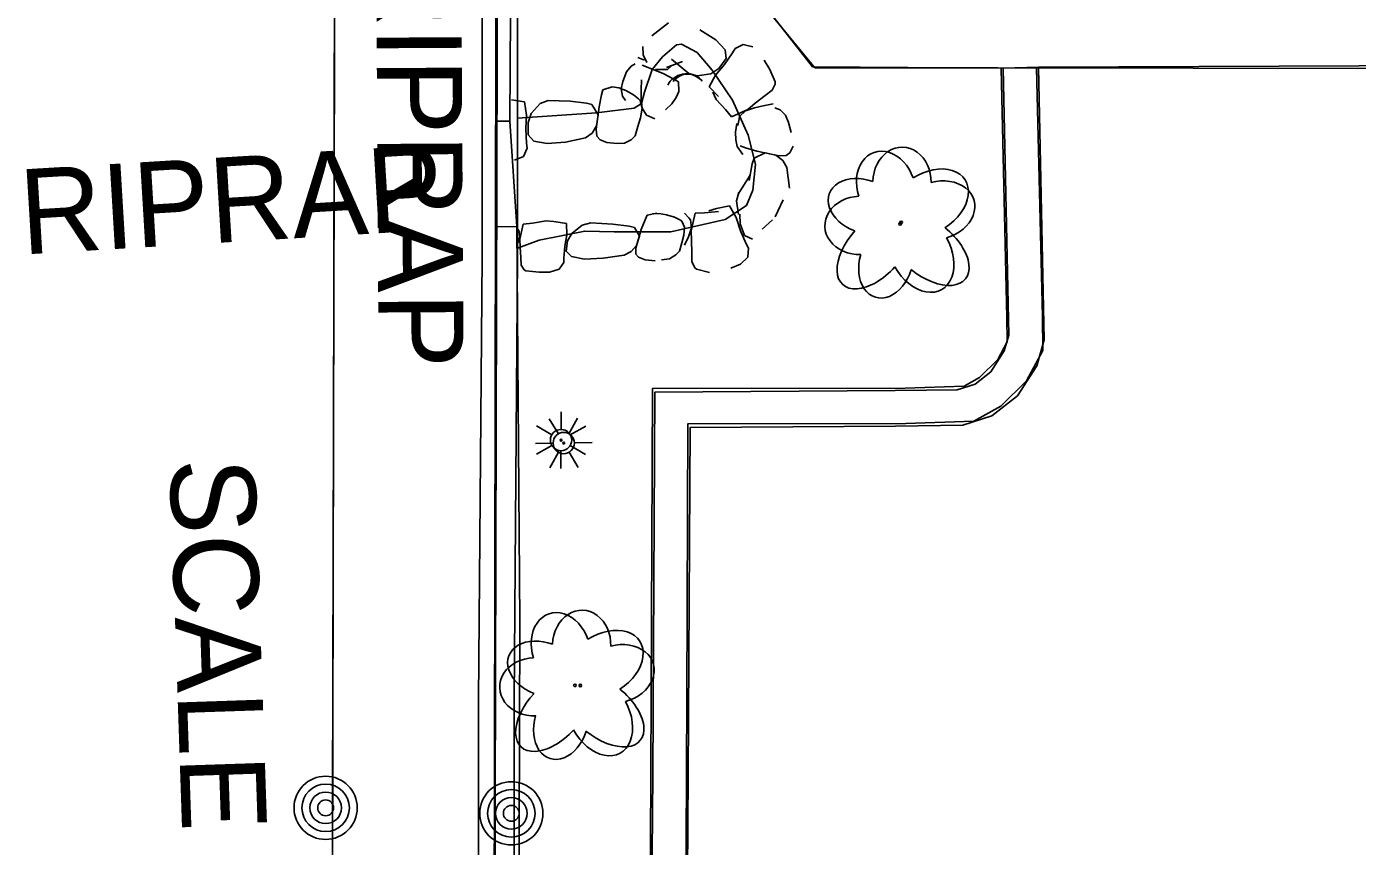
# Model space of a CAD drawing. Extents: x 588843 to 2552415, y 180129 to 269402.
# Drawn here: x 594379 to 594472.9, y 184860.3 to 184918.1 of the extents above; entities that cross this region are included whole.
import ezdxf

# ---------------------------------------------------------------- set-up
doc = ezdxf.new("R2010")
doc.units = 0
for name, color, linetype in [('Default', 7, 'Continuous'), ('E_BLD_Dash', 7, 'Continuous'), ('E_BLD_HvyDash', 7, 'Continuous'), ('E_BLD_Text', 7, 'Continuous'), ('E_DRN', 7, 'Continuous'), ('E_DRN_RipRap', 7, 'Continuous'), ('E_DRN_RipRap_Text', 7, 'Continuous'), ('E_DWY', 7, 'Continuous'), ('E_LAND_Vegetation', 7, 'Continuous'), ('E_LTG', 7, 'Continuous'), ('E_MISCPROP', 7, 'Continuous'), ('E_PATH_Sidewalk', 7, 'Continuous')]:
    doc.layers.add(name, color=color, linetype=linetype)

# ---------------------------------------------------------------- blocks, each defined once
blk = doc.blocks.new('POLE')
at = {"layer": 'Default'}
for radius in [4.46, 3.35, 2.23, 1.12]:
    blk.add_circle((0, 0), radius, dxfattribs=at)
blk = doc.blocks.new('LPOL')
at = {"layer": 'Default'}
for p, q in [((-0.75, 1.3), (-2, 3.46)), ((0.75, 1.3), (2, 3.46)), ((-4, 0), (-1.5, 0)), ((1.5, 0), (4, 0)), ((-2, -3.46), (-0.75, -1.3)), ((2, -3.46), (0.75, -1.3))]:
    blk.add_line(p, q, dxfattribs=at)
for radius in [1.5, 1.5, 1.5, 0.125]:
    blk.add_circle((0, 0), radius, dxfattribs=at)
blk = doc.blocks.new('DTRE')
at = {"layer": 'Default'}
blk.add_circle((-0.18, 0), 0.183, dxfattribs=at)
for centre, major_axis, ratio in [((-1.87, 5.32), (1.36, -4.98), 0.782863), ((4.06, 2.74), (-5.27, -2.93), 0.691916), ((-5.87, 0.15), (4.93, -0.12), 0.832022), ((3.54, -3.71), (-5.01, 4.58), 0.560249), ((-2.49, -5.24), (1.8, 4.86), 0.716896)]:
    blk.add_ellipse(centre, major_axis=major_axis, ratio=ratio, start_param=1.570796, end_param=4.712389, dxfattribs=at)
blk = doc.blocks.new('CULV2')
at = {"layer": 'E_DRN'}
blk.add_arc((19.7, 14.8), 24.6, 216.8699, 323.1301, dxfattribs=at)
blk = doc.blocks.new('RIPRT')
at = {"layer": 'E_DRN_RipRap_Text'}
blk.add_text('RIPRAP', height=12, dxfattribs=at).set_placement((-0.14, -3.59))
blk = doc.blocks.new('LPOL_4')
at = {"layer": 'E_LTG'}
for p, q in [((-2.46, 4.26), (-6.56, 11.36)), ((2.46, 4.26), (6.56, 11.36)), ((-13.12, 0), (-4.92, 0)), ((4.92, 0), (13.12, 0)), ((-6.56, -11.36), (-2.46, -4.26)), ((6.56, -11.36), (2.46, -4.26))]:
    blk.add_line(p, q, dxfattribs=at)
for radius in [4.92, 4.92, 4.92, 0.41]:
    blk.add_circle((0, 0), radius, dxfattribs=at)
blk = doc.blocks.new('RIPRT_3')
at = {"layer": 'E_DRN_RipRap_Text'}
blk.add_text('RIPRAP', height=39.37, dxfattribs=at).set_placement((-0.46, -11.78))
blk = doc.blocks.new('SCAL_1')
at = {"layer": 'E_BLD_HvyDash'}
blk.add_text('SCALE', height=39.37, dxfattribs=at).set_placement((-86.45, -19.68))
blk = doc.blocks.new('CULV2_4')
at = {"layer": 'E_DRN'}
blk.add_arc((64.6, 48.4), 80.7, 216.8699, 323.1301, dxfattribs=at)
blk = doc.blocks.new('DTRE_4')
at = {"layer": 'E_LAND_Vegetation'}
blk.add_circle((-0.6, 0), 0.601, dxfattribs=at)
for centre, major_axis, ratio in [((-6.14, 17.45), (4.46, -16.34), 0.782863), ((13.31, 8.98), (-17.3, -9.61), 0.691916), ((-19.26, 0.5), (16.18, -0.4), 0.832022), ((11.62, -12.16), (-16.44, 15.03), 0.560249), ((-8.18, -17.2), (5.91, 15.93), 0.716896)]:
    blk.add_ellipse(centre, major_axis=major_axis, ratio=ratio, start_param=1.570796, end_param=4.712389, dxfattribs=at)

msp = doc.modelspace()

# ---------------------------------------------------------------- linework, layer by layer
at = {"layer": 'E_BLD_Dash'}
msp.add_lwpolyline([(594400.82, 184942.865), (594400.287, 184739.801), (594411.764, 184739.77), (594412.297, 184942.833)], close=True, dxfattribs=at)
at = {"layer": 'E_BLD_HvyDash'}
msp.add_lwpolyline([(594412.167, 184942.934), (594411.807, 184740.073), (594400.358, 184739.937), (594400.801, 184943.059), (594412.167, 184942.934)], close=True, dxfattribs=at)
at = {"layer": 'E_DRN_RipRap'}
for p, q in [((594423.142, 184917.475), (594424.299, 184918.399)), ((594426.528, 184917.92), (594427.655, 184917.206)), ((594427.655, 184917.206), (594428.308, 184916.491)), ((594429.57, 184916.883), (594429.004, 184916.597)), ((594430.247, 184916.718), (594429.57, 184916.883)), ((594422.152, 184915.969), (594422.605, 184915.758)), ((594422.5, 184916.728), (594422.523, 184916.157)), ((594422.523, 184916.157), (594422.791, 184915.605)), ((594425.738, 184914.832), (594424.516, 184915.83)), ((594428.378, 184915.882), (594427.857, 184915.189)), ((594428.823, 184916.276), (594428.253, 184915.461)), ((594428.308, 184916.491), (594428.378, 184915.882)), ((594429.004, 184916.597), (594428.823, 184916.276)), ((594421.096, 184914.273), (594421.343, 184914.948)), ((594421.343, 184914.948), (594421.668, 184915.351)), ((594421.668, 184915.351), (594421.963, 184915.499)), ((594422.457, 184915.426), (594423.935, 184914.817)), ((594422.679, 184915.333), (594423.393, 184915.03)), ((594424.242, 184915.1), (594423.388, 184915.108)), ((594425.293, 184915.674), (594424.172, 184915.258)), ((594424.54, 184915.382), (594424.242, 184915.1)), ((594427.857, 184915.189), (594427.292, 184914.811)), ((594428.253, 184915.461), (594427.634, 184914.711)), ((594431.45, 184915.113), (594431.06, 184915.763)), ((594431.83, 184914.238), (594431.45, 184915.113)), ((594420.961, 184913.754), (594421.096, 184914.273)), ((594422.379, 184913.684), (594422.396, 184914.387)), ((594423.935, 184914.817), (594424.685, 184914.432)), ((594424.685, 184914.432), (594425.019, 184914.235)), ((594425.019, 184914.235), (594425.036, 184913.558)), ((594426.34, 184914.655), (594425.738, 184914.832)), ((594427.292, 184914.811), (594426.34, 184914.655)), ((594427.634, 184914.711), (594427.179, 184913.879)), ((594431.612, 184913.658), (594431.835, 184914.084)), ((594431.835, 184914.084), (594431.83, 184914.238)), ((594419.409, 184912.486), (594419.585, 184913.312)), ((594419.585, 184913.312), (594419.688, 184913.687)), ((594419.688, 184913.687), (594420.337, 184913.885)), ((594420.337, 184913.885), (594420.803, 184913.81)), ((594420.803, 184913.81), (594421.301, 184913.636)), ((594421.069, 184913.241), (594420.961, 184913.754)), ((594421.269, 184912.915), (594421.069, 184913.241)), ((594421.301, 184913.636), (594421.83, 184913.329)), ((594421.83, 184913.329), (594422.183, 184913.036)), ((594422.183, 184913.036), (594422.316, 184912.914)), ((594422.373, 184913.037), (594422.379, 184913.684)), ((594422.454, 184912.371), (594422.373, 184913.037)), ((594424.84, 184913.13), (594424.539, 184912.696)), ((594425.036, 184913.558), (594424.84, 184913.13)), ((594427.179, 184913.879), (594427.826, 184913.2)), ((594427.434, 184913.506), (594427.666, 184913.003)), ((594427.666, 184913.003), (594428.325, 184912.277)), ((594430.431, 184912.736), (594431.115, 184913.273)), ((594431.115, 184913.273), (594431.612, 184913.658)), ((594414.15, 184912.822), (594413.247, 184912.973)), ((594414.289, 184911.885), (594414.15, 184912.822)), ((594414.614, 184912.011), (594415.259, 184912.711)), ((594415.259, 184912.711), (594415.83, 184912.933)), ((594415.83, 184912.933), (594417.367, 184912.876)), ((594417.367, 184912.876), (594418.525, 184912.743)), ((594418.525, 184912.743), (594418.912, 184912.637)), ((594418.912, 184912.637), (594419.345, 184911.906)), ((594419.206, 184910.898), (594419.409, 184912.486)), ((594422.316, 184912.914), (594422.454, 184912.371)), ((594422.454, 184912.371), (594422.344, 184911.71)), ((594422.745, 184911.892), (594422.454, 184912.371)), ((594424.539, 184912.696), (594424.102, 184912.267)), ((594428.325, 184912.277), (594428.748, 184911.769)), ((594428.748, 184911.769), (594429.901, 184912.299)), ((594429.323, 184911.798), (594429.728, 184912.186)), ((594429.728, 184912.186), (594430.361, 184912.409)), ((594429.901, 184912.299), (594430.431, 184912.736)), ((594430.361, 184912.409), (594430.994, 184912.542)), ((594430.994, 184912.542), (594431.685, 184912.677)), ((594431.816, 184912.411), (594432.174, 184912.254)), ((594432.174, 184912.254), (594432.567, 184911.887)), ((594414.254, 184910.913), (594414.289, 184911.885)), ((594414.4, 184911.369), (594414.614, 184912.011)), ((594414.406, 184910.502), (594414.4, 184911.369)), ((594418.917, 184910.619), (594419.239, 184911.136)), ((594419.239, 184911.136), (594419.345, 184911.906)), ((594422.344, 184911.71), (594422.157, 184911.092)), ((594422.911, 184911.814), (594422.745, 184911.892)), ((594423.341, 184911.639), (594422.911, 184911.814)), ((594429.032, 184910.684), (594429.131, 184911.299)), ((594429.204, 184911.162), (594429.283, 184911.62)), ((594429.283, 184911.62), (594429.323, 184911.798)), ((594432.567, 184911.887), (594432.767, 184911.373)), ((594432.767, 184911.373), (594432.969, 184910.662)), ((594414.294, 184909.919), (594414.254, 184910.913)), ((594414.819, 184910.059), (594414.406, 184910.502)), ((594418.455, 184910.299), (594417.045, 184909.995)), ((594418.455, 184910.299), (594418.917, 184910.619)), ((594419.265, 184910.402), (594419.206, 184910.898)), ((594419.486, 184910.157), (594419.265, 184910.402)), ((594421.946, 184910.424), (594421.682, 184910.144)), ((594422.157, 184911.092), (594421.946, 184910.424)), ((594429.046, 184910.144), (594429.032, 184910.684)), ((594414.074, 184908.984), (594414.343, 184909.554)), ((594414.343, 184909.554), (594414.294, 184909.919)), ((594415.749, 184909.884), (594414.819, 184910.059)), ((594417.045, 184909.995), (594415.749, 184909.884)), ((594419.96, 184909.951), (594419.486, 184910.157)), ((594420.678, 184909.893), (594419.96, 184909.951)), ((594421.215, 184909.902), (594420.678, 184909.893)), ((594421.682, 184910.144), (594421.215, 184909.902)), ((594429.142, 184909.67), (594429.046, 184910.144)), ((594429.56, 184909.113), (594429.142, 184909.67)), ((594429.73, 184909.588), (594429.365, 184909.722)), ((594430.541, 184909.344), (594429.73, 184909.588)), ((594430.353, 184908.847), (594431.114, 184909.234)), ((594432.109, 184909.014), (594430.541, 184909.344)), ((594431.873, 184909.066), (594431.114, 184909.234)), ((594432.869, 184909.243), (594432.608, 184909.036)), ((594433.109, 184909.713), (594432.869, 184909.243)), ((594413.452, 184908.707), (594414.074, 184908.984)), ((594429.997, 184907.283), (594430.218, 184908.458)), ((594430.218, 184908.458), (594430.353, 184908.847)), ((594432.365, 184908.697), (594431.873, 184909.066)), ((594432.608, 184909.036), (594432.109, 184909.014)), ((594432.649, 184908.199), (594432.365, 184908.697)), ((594429.231, 184906.313), (594430.069, 184907.651)), ((594432.649, 184908.199), (594432.845, 184906.731)), ((594429.094, 184905.841), (594429.279, 184906.441)), ((594428.613, 184905.485), (594427.693, 184905.296)), ((594429.077, 184904.659), (594428.613, 184905.485)), ((594429.24, 184904.887), (594429.094, 184905.841)), ((594432.392, 184905.915), (594431.823, 184904.707)), ((594422.666, 184904.515), (594422.814, 184904.827)), ((594422.814, 184904.827), (594423.494, 184904.976)), ((594423.178, 184904.937), (594423.656, 184904.941)), ((594423.656, 184904.941), (594424.175, 184904.867)), ((594424.175, 184904.867), (594424.735, 184904.688)), ((594424.735, 184904.688), (594425.115, 184904.495)), ((594425.432, 184904.983), (594425.747, 184904.643)), ((594425.747, 184904.643), (594425.864, 184904.502)), ((594426.19, 184904.977), (594425.911, 184903.739)), ((594426.848, 184905.005), (594426.19, 184904.977)), ((594427.824, 184905.087), (594426.848, 184905.005)), ((594427.693, 184905.296), (594427.162, 184905.141)), ((594429.385, 184903.737), (594429.077, 184904.659)), ((594429.365, 184904.217), (594429.343, 184904.896)), ((594413.627, 184903.872), (594413.747, 184903.766)), ((594413.747, 184903.766), (594413.824, 184903.307)), ((594414.057, 184904.193), (594413.814, 184903.134)), ((594414.711, 184904.278), (594414.057, 184904.193)), ((594415.677, 184904.439), (594414.711, 184904.278)), ((594416.215, 184904.389), (594415.677, 184904.439)), ((594417.111, 184904.24), (594416.215, 184904.389)), ((594417.143, 184903.45), (594417.111, 184904.24)), ((594417.486, 184903.548), (594418.22, 184904.119)), ((594418.22, 184904.119), (594418.824, 184904.291)), ((594418.824, 184904.291), (594420.372, 184904.205)), ((594420.372, 184904.205), (594421.527, 184904.064)), ((594421.527, 184904.064), (594421.907, 184903.965)), ((594421.907, 184903.965), (594422.26, 184903.342)), ((594422.003, 184902.5), (594422.392, 184903.826)), ((594422.392, 184903.826), (594422.666, 184904.515)), ((594425.115, 184904.495), (594425.259, 184904.413)), ((594425.259, 184904.413), (594425.441, 184903.983)), ((594425.441, 184903.983), (594425.379, 184903.42)), ((594425.926, 184903.945), (594425.72, 184903.307)), ((594425.864, 184904.502), (594425.926, 184903.945)), ((594425.911, 184903.739), (594425.937, 184903.052)), ((594429.676, 184903.408), (594429.365, 184904.217)), ((594429.775, 184902.822), (594429.385, 184903.737)), ((594431.631, 184904.5), (594430.908, 184903.853)), ((594413.824, 184903.307), (594413.636, 184902.756)), ((594413.814, 184903.134), (594413.858, 184902.564)), ((594416.994, 184902.636), (594417.143, 184903.45)), ((594417.1, 184902.288), (594417.195, 184903.015)), ((594417.195, 184903.015), (594417.486, 184903.548)), ((594421.678, 184902.273), (594422.063, 184902.699)), ((594422.063, 184902.699), (594422.26, 184903.342)), ((594425.237, 184902.882), (594425.073, 184902.299)), ((594425.379, 184903.42), (594425.237, 184902.882)), ((594425.72, 184903.307), (594425.441, 184902.723)), ((594425.937, 184903.052), (594425.948, 184902.183)), ((594430.229, 184903.145), (594429.676, 184903.408)), ((594429.951, 184902.499), (594429.775, 184902.822)), ((594413.858, 184902.564), (594413.893, 184901.841)), ((594413.893, 184901.841), (594413.914, 184901.317)), ((594416.92, 184901.802), (594416.994, 184902.636)), ((594416.927, 184901.495), (594416.92, 184901.802)), ((594417.467, 184901.906), (594417.1, 184902.288)), ((594418.388, 184901.736), (594417.467, 184901.906)), ((594419.711, 184901.797), (594418.388, 184901.736)), ((594421.173, 184902.017), (594419.711, 184901.797)), ((594421.173, 184902.017), (594421.678, 184902.273)), ((594422.004, 184902.083), (594422.003, 184902.5)), ((594422.199, 184901.872), (594422.004, 184902.083)), ((594422.656, 184901.688), (594422.199, 184901.872)), ((594424.371, 184901.764), (594423.826, 184901.68)), ((594424.827, 184902.029), (594424.371, 184901.764)), ((594425.073, 184902.299), (594424.827, 184902.029)), ((594425.948, 184902.183), (594425.952, 184901.554)), ((594429.395, 184901.38), (594429.893, 184901.867)), ((594429.893, 184901.867), (594429.951, 184902.499)), ((594413.914, 184901.317), (594414.127, 184900.972)), ((594414.127, 184900.972), (594414.254, 184900.91)), ((594414.254, 184900.91), (594415.178, 184900.806)), ((594415.178, 184900.806), (594415.927, 184900.806)), ((594415.927, 184900.806), (594416.589, 184901.024)), ((594416.589, 184901.024), (594416.927, 184901.495)), ((594423.375, 184901.621), (594422.656, 184901.688)), ((594425.952, 184901.554), (594426.155, 184901.118)), ((594426.155, 184901.118), (594426.28, 184901.029)), ((594426.28, 184901.029), (594427.204, 184900.799)), ((594428.694, 184901.089), (594429.395, 184901.38))]:
    msp.add_line(p, q, dxfattribs=at)
msp.add_lwpolyline([(594413.663, 184911.669), (594419.235, 184912.05), (594421.895, 184912.371), (594422.395, 184912.701), (594422.627, 184913.513), (594423.155, 184915.119), (594423.878, 184915.993), (594424.869, 184916.858), (594425.217, 184916.894), (594426.332, 184916.304), (594427.394, 184915.054), (594428.821, 184912.957), (594429.935, 184910.475), (594430.434, 184908.44), (594430.246, 184906.602), (594429.799, 184905.513), (594428.299, 184904.523), (594424.47, 184903.659), (594420.481, 184903.652), (594418.402, 184903.707), (594415.18, 184903.074), (594413.659, 184902.504)], dxfattribs=at)
at = {"layer": 'E_DWY'}
for points in [[(594400.349, 185071.926), (594402.259, 185069.795), (594403.773, 185067.566), (594406.001, 185063.961), (594407.579, 185060.812), (594409.56, 185056.502), (594410.714, 185053.097), (594411.885, 185049.035), (594412.586, 185045.165), (594412.942, 185041.064), (594413.197, 185028.852), (594413.362, 185012.493), (594413.404, 185000.074), (594413.647, 184951.762), (594413.305, 184941.66), (594413.122, 184911.47)], [(594421.964, 184675.588), (594415.823, 184703.87), (594411.734, 184723.077), (594411.259, 184727.356), (594410.681, 184734.111), (594410.956, 184807.45), (594410.916, 184870.642), (594411.159, 184901.905), (594411.175, 184939.878)], [(594424.407, 184676.119), (594418.267, 184704.395), (594414.205, 184723.476), (594413.747, 184727.6), (594413.182, 184734.213), (594413.456, 184807.446), (594413.416, 184870.633), (594413.659, 184901.895), (594413.675, 184939.877)], [(594447.766, 184915.172), (594448.178, 184897.648), (594448.191, 184895.904), (594447.528, 184894.66), (594446.243, 184893.389), (594445.147, 184892.781), (594441.009, 184892.634), (594423.188, 184892.615), (594423.097, 184870.832), (594423.023, 184855.187), (594423.016, 184838.704), (594422.949, 184807.699), (594422.802, 184779.993), (594422.789, 184749.177), (594422.835, 184730.017), (594429.933, 184730.135)], [(594423.096, 184851.355), (594423.203, 184865.373), (594423.352, 184892.346), (594440.301, 184892.458), (594444.662, 184892.513), (594445.928, 184892.919), (594447.034, 184893.789), (594447.975, 184895.255), (594448.299, 184896.375), (594447.903, 184915.216)], [(594450.266, 184915.231), (594450.678, 184897.687), (594450.695, 184895.287), (594449.555, 184893.149), (594447.756, 184891.37), (594445.835, 184890.304), (594441.055, 184890.135), (594425.677, 184890.118), (594425.597, 184870.82), (594425.523, 184855.181), (594425.516, 184838.701), (594425.449, 184807.69), (594425.302, 184779.986), (594425.289, 184749.18), (594425.29, 184748.717)], [(594425.334, 184748.665), (594425.309, 184753.722), (594425.449, 184777.312), (594425.479, 184799.41), (594425.469, 184820.536), (594425.596, 184851.34), (594425.703, 184865.357), (594425.839, 184889.862), (594440.326, 184889.958), (594445.068, 184890.018), (594447.121, 184890.675), (594448.91, 184892.085), (594450.276, 184894.211), (594450.806, 184896.048), (594450.402, 184915.268)], [(594447.903, 184915.216), (594450.402, 184915.268), (594489.978, 184915.432), (594516.917, 184915.192)], [(594412.098, 184904.021), (594413.61, 184904.033), (594413.122, 184911.47), (594412.111, 184911.477)], [(594413.61, 184904.033), (594413.831, 184876.2), (594413.677, 184831.019), (594413.363, 184779.014), (594413.273, 184758.117), (594413.157, 184745.675)]]:
    msp.add_lwpolyline(points, dxfattribs=at)
at = {"layer": 'E_PATH_Sidewalk'}
for points in [[(594413.678, 184940.789), (594434.634, 184915.224), (594447.534, 184915.218), (594488.883, 184915.16), (594519.388, 184915.85)], [(594447.903, 184915.216), (594434.472, 184915.3), (594424.145, 184928.509)]]:
    msp.add_lwpolyline(points, dxfattribs=at)

# ---------------------------------------------------------------- block references
at = {"layer": 'E_BLD_Text', "xscale": 0.1524003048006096, "yscale": 0.1524003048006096, "rotation": -88.07286364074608}
msp.add_blockref('SCAL_1', (594392.566, 184874.533), dxfattribs=at)
at = {"layer": 'E_DRN'}
for name, p, xscale, yscale, rotation in [('CULV2_4', (594426.537, 184914.421), 0.017999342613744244, 0.01799934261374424, -169.40472757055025), ('CULV2', (594426.691, 184914.296), 0.051928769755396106, 0.05192876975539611, -179.2699623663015)]:
    msp.add_blockref(name, p, dxfattribs=dict(at, xscale=xscale, yscale=yscale, rotation=rotation))
at = {"layer": 'E_DRN_RipRap_Text'}
for name, p, xscale, yscale, rotation in [('RIPRT', (594405.484, 184923.83), 0.49999999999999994, 0.4999999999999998, -89.6710262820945), ('RIPRT_3', (594378.707, 184903.848), 0.15240030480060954, 0.15240030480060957, 3.4338469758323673)]:
    msp.add_blockref(name, p, dxfattribs=dict(at, xscale=xscale, yscale=yscale, rotation=rotation))
at = {"layer": 'E_LAND_Vegetation'}
for name, p, xscale, yscale, rotation in [('DTRE_4', (594440.736, 184904.214), 0.15240030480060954, 0.15240030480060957, 3.4338469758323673), ('DTRE', (594440.712, 184904.234), 0.49999999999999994, 0.4999999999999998, -89.6710262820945), ('DTRE_4', (594417.803, 184871.663), 0.15240030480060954, 0.15240030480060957, 3.4338469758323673), ('DTRE', (594418.088, 184871.561), 0.4999999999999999, 0.49999999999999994, -90.39935623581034)]:
    msp.add_blockref(name, p, dxfattribs=dict(at, xscale=xscale, yscale=yscale, rotation=rotation))
at = {"layer": 'E_LTG'}
for name, p, xscale, yscale, rotation in [('LPOL_4', (594416.923, 184888.756), 0.15240030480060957, 0.15240030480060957, 0.8014450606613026), ('LPOL', (594416.732, 184888.963), 0.4999999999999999, 0.49999999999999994, -90.39935623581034)]:
    msp.add_blockref(name, p, dxfattribs=dict(at, xscale=xscale, yscale=yscale, rotation=rotation))
at = {"layer": 'E_MISCPROP', "xscale": 0.4999999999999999, "yscale": 0.49999999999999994, "rotation": -90.39935623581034}
for p in [(594400.128, 184863.02), (594413.223, 184862.632)]:
    msp.add_blockref('POLE', p, dxfattribs=at)

doc.saveas('drawing.dxf')
